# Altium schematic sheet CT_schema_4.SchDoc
size 381 x 356 mm
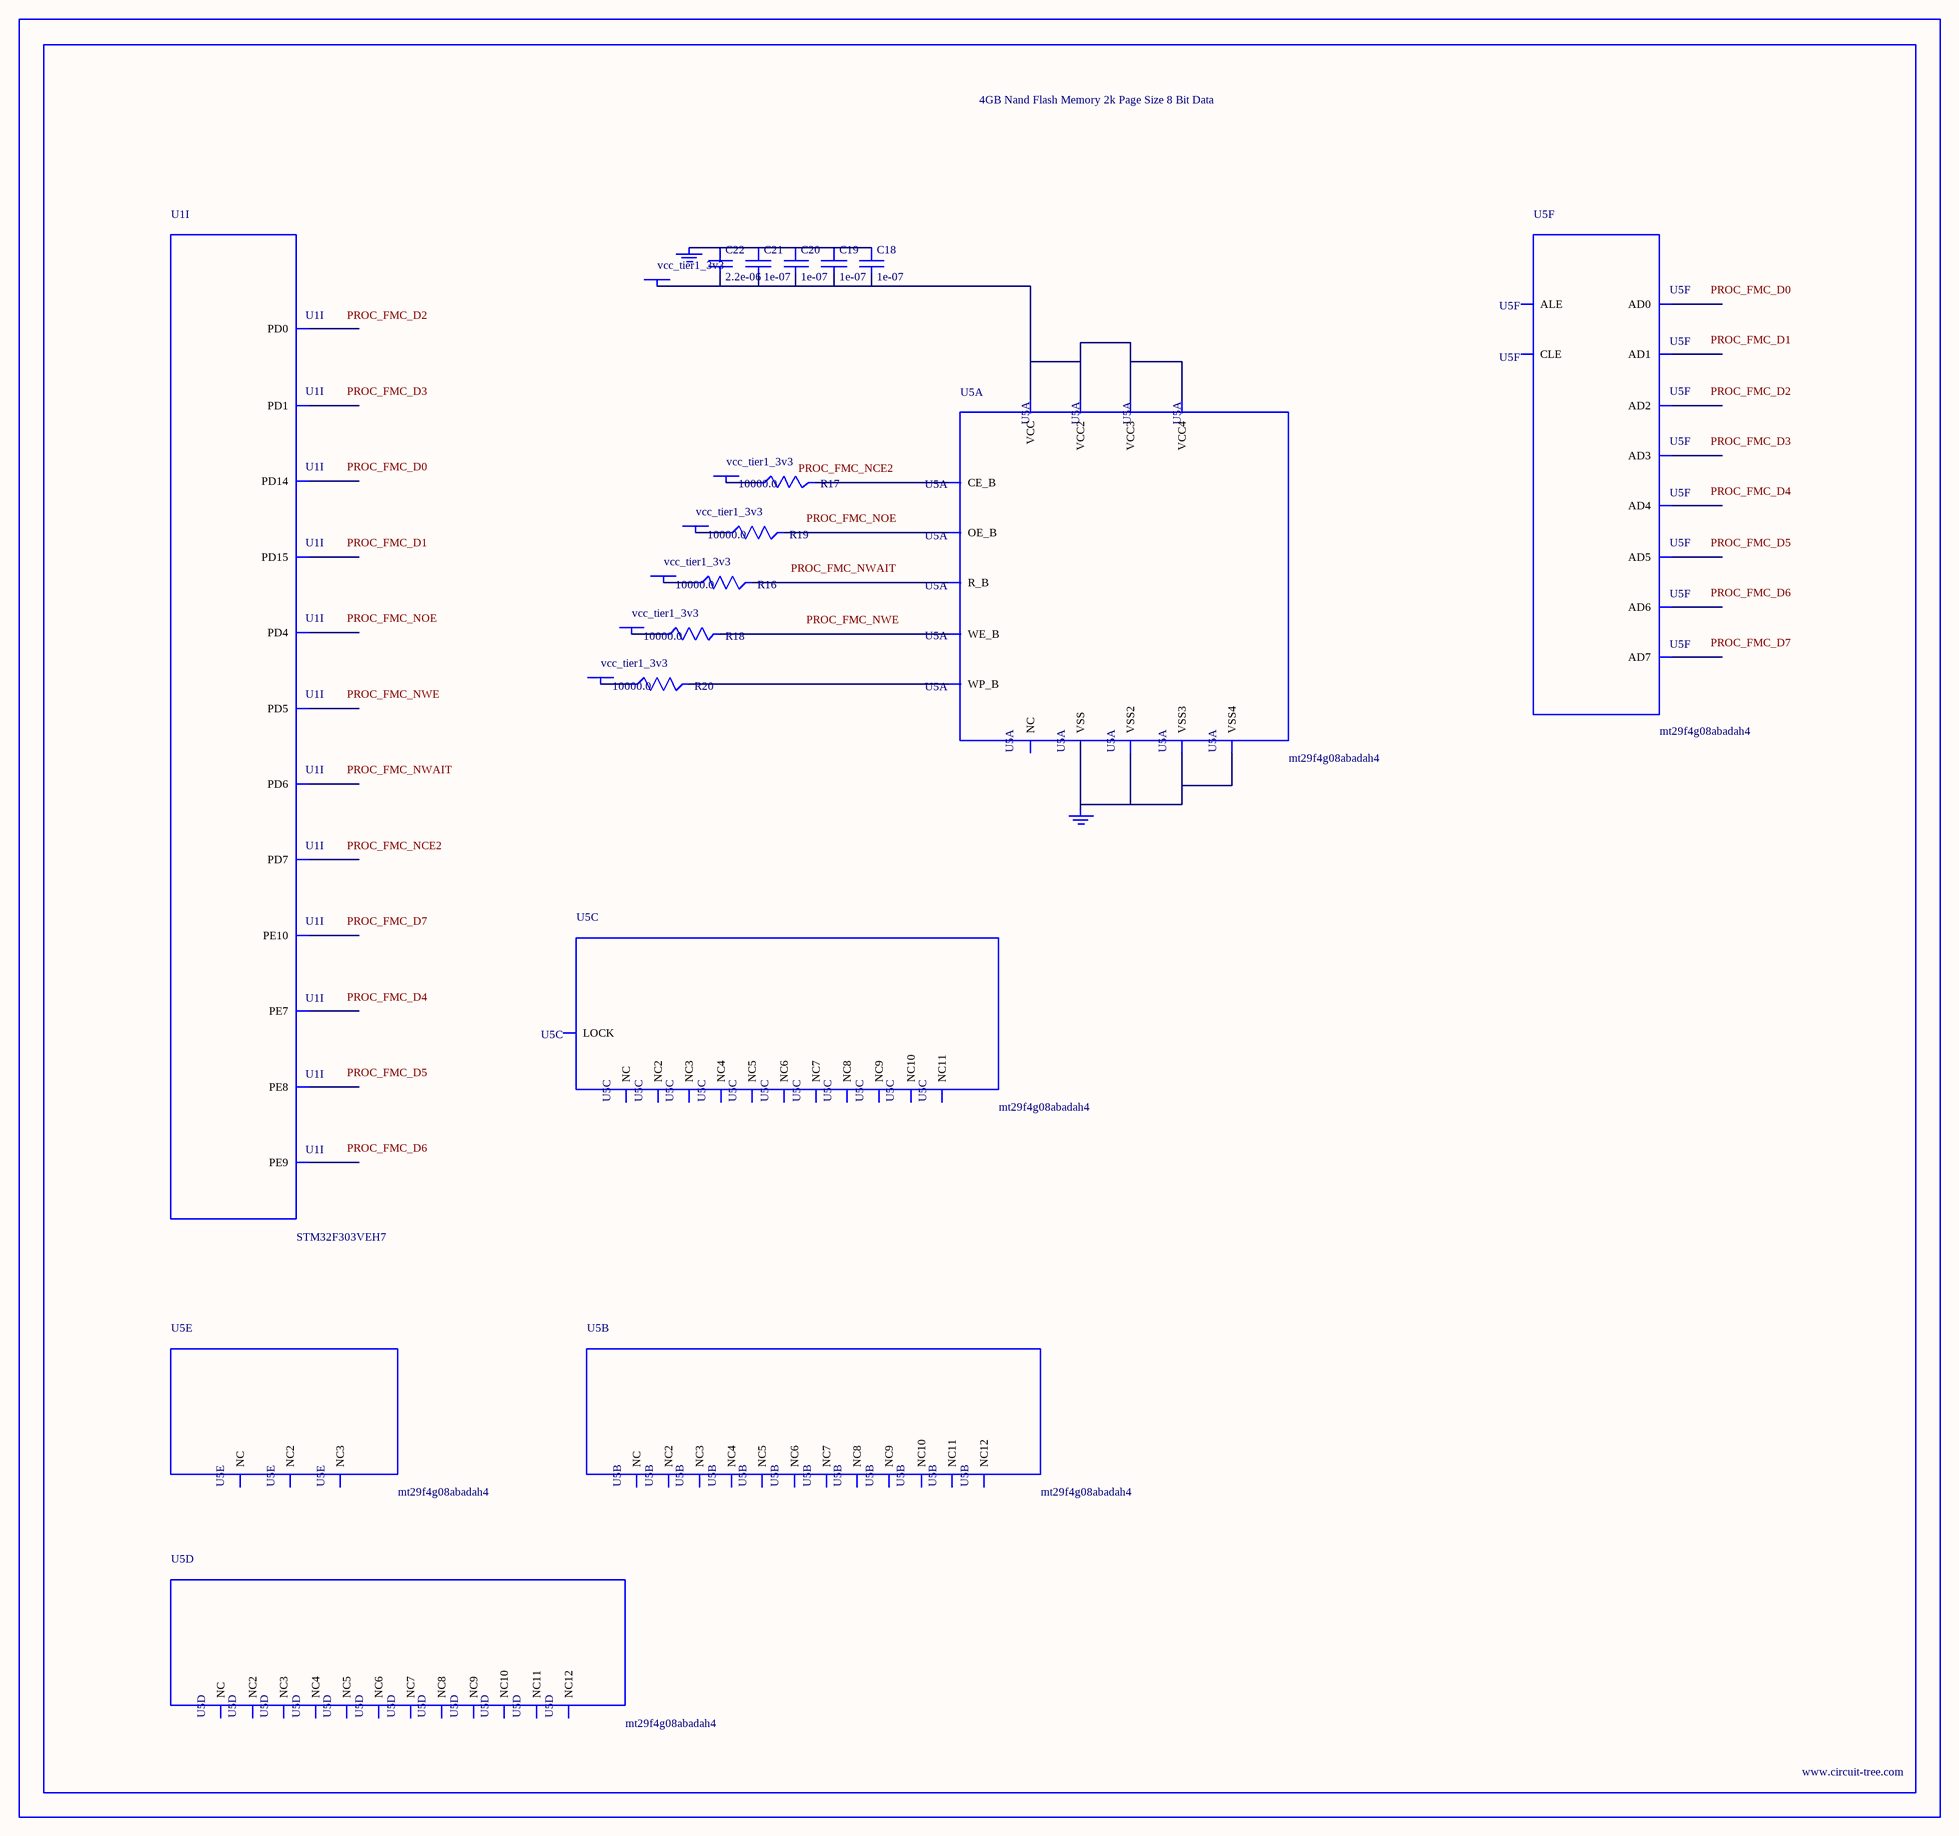
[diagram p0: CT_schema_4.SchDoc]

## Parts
BORDER3  (no value)
C18  1e-07  [C0402]
C19  1e-07  [C0402]
C20  1e-07  [C0402]
C21  1e-07  [C0402]
C22  2.2e-06  [C0603]
GND_INSTANCE_3_0  (no value)
GND_INSTANCE_3_1  (no value)
POWER_INSTANCE_3_0  vcc_tier1_3v3
POWER_INSTANCE_3_1  vcc_tier1_3v3
POWER_INSTANCE_3_2  vcc_tier1_3v3
POWER_INSTANCE_3_3  vcc_tier1_3v3
POWER_INSTANCE_3_4  vcc_tier1_3v3
POWER_INSTANCE_3_5  vcc_tier1_3v3
R16  10000.0  [R0603]
R17  10000.0  [R0603]
R18  10000.0  [R0603]
R19  10000.0  [R0603]
R20  10000.0  [R0603]
U1  STM32F303VEH7  [UFBGA100]  (part I of 10)
U5  mt29f4g08abadah4  [VFBGA-63]  (parts A,B,C,D,E,F of 6)

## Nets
NetC18_1: C18.1 C19.1 C20.1 C21.1 C22.1 GND_INSTANCE_3_0.0(GND)
NetC18_2: C18.2 C19.2 C20.2 C21.2 C22.2 POWER_INSTANCE_3_0.0(PWR) U5.D3(VCC) U5.G4(VCC2) U5.H8(VCC3) U5.J6(VCC4)
NetGND_INSTANCE_3_1_0: GND_INSTANCE_3_1.0(GND) U5.C5(VSS) U5.F7(VSS2) U5.K3(VSS3) U5.K8(VSS4)
NetPOWER_INSTANCE_3_1_0: POWER_INSTANCE_3_1.0(PWR) R16.1
NetPOWER_INSTANCE_3_2_0: POWER_INSTANCE_3_2.0(PWR) R17.1
NetPOWER_INSTANCE_3_3_0: POWER_INSTANCE_3_3.0(PWR) R18.1
NetPOWER_INSTANCE_3_4_0: POWER_INSTANCE_3_4.0(PWR) R19.1
NetPOWER_INSTANCE_3_5_0: POWER_INSTANCE_3_5.0(PWR) R20.1
NetR16_2: R16.2 U5.C8(R_B)
NetR17_2: R17.2 U5.C6(CE_B)
NetR18_2: R18.2 U5.C7(WE_B)
NetR19_2: R19.2 U5.D4(OE_B)
NetR20_2: R20.2 U5.C3(WP_B)

Not connected (* = marked no-connect by the designer): U1 A5(PD7) A6(PD5) B6(PD6) B7(PD4) B9(PD1) C9(PD0) H10(PD15) H11(PD14) L7(PE8) L8(PE10) M7(PE7) M8(PE9); U5 A1(NC) A2(NC3) A9(NC4) A10(NC2) B1(NC5) B9(NC7) B10(NC6) C4(ALE) D5(CLE) D6(NC8) D7(NC9) D8(NC10) E3(NC11) E4(NC12) E5(NC) E6(NC2) E7(NC3) E8(NC4) F3(NC5) F4(NC6) F5(NC7) F6(NC8) F8(NC9) G3(NC) G5(LOCK) G6(NC10) G7(NC11) G8(NC) H3(NC2) H4(AD0) H5(NC3) H6(NC4) H7(NC5) J3(NC6) J4(AD1) J5(NC7) J7(AD5) J8(AD7) K4(AD2) K5(AD3) K6(AD4) K7(AD6) L1(NC8) L2(NC10) L9(NC11) L10(NC9) M1(NC12) M2(NC2) M9(NC3) M10(NC)

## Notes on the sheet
- Labels drawn without touching a wire or pin: PROC_FMC_D0, PROC_FMC_D1, PROC_FMC_D2, PROC_FMC_D3, PROC_FMC_D4, PROC_FMC_D5, PROC_FMC_D6, PROC_FMC_D7, PROC_FMC_NCE2, PROC_FMC_NOE, PROC_FMC_NWAIT, PROC_FMC_NWE

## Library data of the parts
BORDER3 = BORDER_PAGE3
C18-C21 = C0402C104K3RACTU
C22 = C0603C225K8RACTU
GND_INSTANCE_3_0 GND_INSTANCE_3_1 = GND
POWER_INSTANCE_3_0-POWER_INSTANCE_3_5 = PWR
R16-R20 = RC0603JR-0710KL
